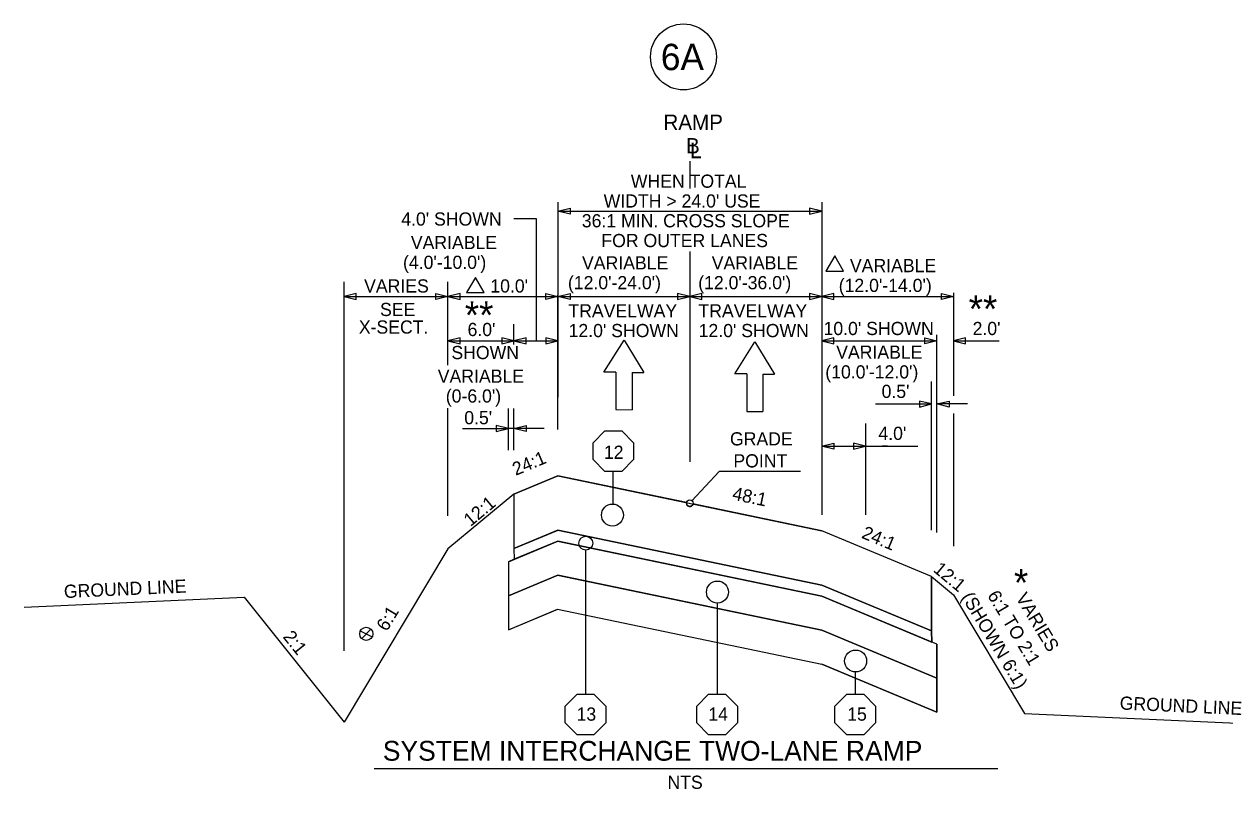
# Model space of a CAD drawing. Extents: x 4649 to 5578, y 4853 to 5383.
# Drawn here: x 5020.7 to 5130, y 5063.7 to 5133.3 of the extents above; entities that cross this region are included whole.
import ezdxf

# ---------------------------------------------------------------- set-up
doc = ezdxf.new("R2010")
doc.units = 0
for name, color, linetype in [('Level 25', 7, 'Continuous'), ('RD_QTY_Miscl_1', 7, 'Continuous'), ('RD_QTY_Miscl_2', 7, 'Continuous'), ('RD_QTY_Miscl_3', 7, 'Continuous'), ('RD_QTY_Miscl_4', 7, 'Continuous'), ('RD_SHT_Bndy', 7, 'Continuous'), ('RD_SHT_Typical', 7, 'Continuous'), ('RD_Sketch1', 7, 'Continuous'), ('RD_Sketch2', 7, 'Continuous'), ('RD_TX_TypSect', 7, 'Continuous')]:
    doc.layers.add(name, color=color, linetype=linetype)

msp = doc.modelspace()

# ---------------------------------------------------------------- linework, layer by layer
at = {"layer": 'Level 25'}
for p, q in [((5083.98, 5092.59), (5081.49, 5089.93)), ((5091.37, 5092.59), (5083.98, 5092.59))]:
    msp.add_line(p, q, dxfattribs=at)
msp.add_circle((5080.73, 5130.3), 3, dxfattribs=at)
at = {"layer": 'RD_QTY_Miscl_1'}
for p, q in [((5069.3, 5092.2), (5065.31, 5090.54)), ((5081.01, 5089.76), (5069.3, 5092.2)), ((5065.31, 5090.54), (5065.31, 5085.58)), ((5093.3, 5087.2), (5081.59, 5089.64)), ((5065.31, 5085.58), (5069.31, 5087.25)), ((5069.31, 5087.25), (5093.3, 5082.25)), ((5103.29, 5083.04), (5093.3, 5087.2)), ((5103.29, 5078.09), (5103.29, 5083.04)), ((5093.3, 5082.25), (5103.29, 5078.09))]:
    msp.add_line(p, q, dxfattribs=at)
msp.add_arc((5081.3, 5089.7), 0.3, 168.2319, 348.2319, dxfattribs=at)
at = {"layer": 'RD_QTY_Miscl_2'}
for p, q in [((5069.31, 5087.25), (5065.31, 5085.58)), ((5065.32, 5084.6), (5069.29, 5086.25)), ((5069.29, 5086.25), (5093.3, 5081.25)), ((5093.3, 5082.25), (5069.31, 5087.25)), ((5065.31, 5085.58), (5065.32, 5084.6)), ((5103.29, 5078.09), (5093.3, 5082.25)), ((5093.3, 5081.25), (5103.33, 5077.07)), ((5103.33, 5077.07), (5103.29, 5078.09))]:
    msp.add_line(p, q, dxfattribs=at)
at = {"layer": 'RD_QTY_Miscl_3'}
for p, q in [((5069.29, 5086.25), (5065.32, 5084.6)), ((5093.3, 5081.25), (5069.29, 5086.25)), ((5065.32, 5084.6), (5064.81, 5084.38)), ((5064.81, 5084.38), (5064.81, 5081.29)), ((5064.81, 5081.29), (5069.29, 5083.16)), ((5069.29, 5083.16), (5093.3, 5078.15)), ((5093.3, 5078.15), (5103.79, 5073.78)), ((5103.79, 5073.78), (5103.79, 5076.87))]:
    msp.add_line(p, q, dxfattribs=at)
msp.add_lwpolyline([(5103.79, 5076.87), (5103.33, 5077.07), (5093.3, 5081.25)], dxfattribs=at)
at = {"layer": 'RD_QTY_Miscl_4'}
for p, q in [((5069.29, 5083.16), (5064.81, 5081.29)), ((5093.3, 5078.15), (5069.29, 5083.16)), ((5064.81, 5081.29), (5064.81, 5078.2)), ((5064.81, 5078.2), (5069.28, 5080.06)), ((5069.28, 5080.06), (5093.3, 5075.06)), ((5103.79, 5073.78), (5093.3, 5078.15)), ((5093.3, 5075.06), (5103.79, 5070.68)), ((5103.79, 5070.68), (5103.79, 5073.78))]:
    msp.add_line(p, q, dxfattribs=at)
at = {"layer": 'RD_SHT_Bndy'}
for p, q in [((5073.5, 5101.62), (5075.32, 5104.54)), ((5075.32, 5104.54), (5077.11, 5101.61)), ((5085.39, 5101.46), (5087.22, 5104.37)), ((5087.22, 5104.37), (5089, 5101.45)), ((5074.59, 5101.62), (5073.5, 5101.62)), ((5074.59, 5101.62), (5074.59, 5098.22)), ((5076.05, 5101.61), (5077.11, 5101.61)), ((5076.05, 5101.61), (5076.05, 5098.21)), ((5086.49, 5101.46), (5085.39, 5101.46)), ((5086.49, 5101.46), (5086.49, 5098.06)), ((5087.94, 5101.45), (5089, 5101.45)), ((5087.94, 5101.45), (5087.94, 5098.05)), ((5074.59, 5098.22), (5076.05, 5098.21)), ((5086.49, 5098.06), (5087.94, 5098.05))]:
    msp.add_line(p, q, dxfattribs=at)
at = {"layer": 'RD_SHT_Typical'}
for p, q in [((5065.31, 5090.54), (5069.3, 5092.2)), ((5065.31, 5090.53), (5059.31, 5085.54)), ((5065.31, 5090.54), (5065.31, 5085.58)), ((5064.81, 5084.38), (5069.31, 5086.26)), ((5065.31, 5085.58), (5069.33, 5087.26)), ((5103.29, 5083.04), (5093.3, 5087.2)), ((5059.31, 5085.54), (5049.87, 5069.8)), ((5064.81, 5084.38), (5064.81, 5078.2)), ((5064.81, 5081.29), (5069.31, 5083.17)), ((5103.29, 5083.04), (5105.29, 5081.36)), ((5103.29, 5083.04), (5103.29, 5078.09)), ((5103.29, 5078.09), (5093.3, 5082.25)), ((5040.78, 5081.15), (5049.87, 5069.8)), ((5103.79, 5076.87), (5093.3, 5081.25)), ((5105.29, 5081.36), (5111.76, 5070.58)), ((5064.81, 5078.2), (5069.3, 5080.07)), ((5103.79, 5073.78), (5093.3, 5078.15)), ((5103.79, 5076.87), (5103.79, 5070.68)), ((5103.79, 5070.68), (5093.3, 5075.06))]:
    msp.add_line(p, q, dxfattribs=at)
for points in [[(5069.3, 5092.2), (5093.3, 5087.2)], [(5069.28, 5086.25), (5093.3, 5081.25)], [(5069.31, 5087.25), (5093.3, 5082.25)], [(5069.28, 5083.16), (5093.3, 5078.15)], [(5069.28, 5080.06), (5093.3, 5075.06)]]:
    msp.add_lwpolyline(points, dxfattribs=at)
at = {"layer": 'RD_Sketch1'}
for p, q in [((5020.75, 5080.24), (5040.78, 5081.15)), ((5111.76, 5070.58), (5133.85, 5069.57))]:
    msp.add_line(p, q, dxfattribs=at)
at = {"layer": 'RD_Sketch2'}
for points in [[(5076.19, 5095.21), (5076.19, 5093.68), (5075.11, 5092.6), (5073.58, 5092.6), (5072.5, 5093.68), (5072.5, 5095.21), (5073.58, 5096.29), (5075.11, 5096.29)], [(5073.67, 5071.25), (5073.67, 5069.72), (5072.59, 5068.64), (5071.06, 5068.64), (5069.98, 5069.72), (5069.98, 5071.25), (5071.06, 5072.33), (5072.59, 5072.33)], [(5085.63, 5071.25), (5085.63, 5069.72), (5084.55, 5068.64), (5083.02, 5068.64), (5081.93, 5069.72), (5081.93, 5071.25), (5083.02, 5072.33), (5084.55, 5072.33)], [(5098.2, 5071.25), (5098.2, 5069.72), (5097.12, 5068.64), (5095.59, 5068.64), (5094.51, 5069.72), (5094.51, 5071.25), (5095.59, 5072.33), (5097.12, 5072.33)]]:
    msp.add_lwpolyline(points, close=True, dxfattribs=at)
at = {"layer": 'RD_TX_TypSect'}
for p, q in [((5081.3, 5120.83), (5081.3, 5118.34)), ((5069.3, 5117.1), (5069.3, 5099.34)), ((5093.3, 5117.1), (5093.3, 5088.64)), ((5069.3, 5116.26), (5093.3, 5116.26)), ((5067.37, 5115.58), (5065.31, 5115.58)), ((5067.37, 5104.47), (5067.37, 5115.58)), ((5081.3, 5112.61), (5081.3, 5093.46)), ((5049.87, 5076.28), (5049.87, 5109.84)), ((5059.31, 5102.25), (5059.31, 5109.84)), ((5049.87, 5108.51), (5059.31, 5108.51)), ((5059.31, 5108.51), (5069.3, 5108.51)), ((5069.3, 5096.42), (5069.3, 5108.63)), ((5069.3, 5108.51), (5081.3, 5108.51)), ((5081.3, 5108.51), (5093.3, 5108.51)), ((5093.3, 5108.51), (5105.29, 5108.51)), ((5105.29, 5108.85), (5105.29, 5099.48)), ((5065.31, 5104.13), (5065.31, 5105.98)), ((5103.79, 5087.05), (5103.79, 5105.01)), ((5059.31, 5104.47), (5065.31, 5104.47)), ((5065.31, 5104.47), (5069.3, 5104.47)), ((5093.3, 5104.47), (5103.79, 5104.47)), ((5105.29, 5104.47), (5109.43, 5104.47)), ((5103.29, 5087.26), (5103.29, 5100.77)), ((5059.31, 5088.55), (5059.31, 5098.35)), ((5064.81, 5094.54), (5064.81, 5098.32)), ((5065.31, 5094.54), (5065.31, 5098.32)), ((5098.2, 5098.73), (5103.29, 5098.73)), ((5106.55, 5098.73), (5103.79, 5098.73)), ((5105.29, 5097.87), (5105.29, 5085.8)), ((5060.63, 5096.5), (5064.81, 5096.5)), ((5068.07, 5096.5), (5064.81, 5096.5)), ((5097.29, 5096.95), (5097.29, 5088.64)), ((5093.3, 5094.9), (5102.06, 5094.9)), ((5099.29, 5094.9), (5098.79, 5094.9)), ((5074.34, 5089.62), (5074.34, 5092.6)), ((5065.31, 5085.58), (5065.32, 5084.6)), ((5071.82, 5085.44), (5071.82, 5072.33)), ((5083.78, 5080.62), (5083.78, 5072.33)), ((5051.33, 5078.09), (5052.41, 5077.54)), ((5051.46, 5077.4), (5052.28, 5078.24)), ((5103.29, 5078.09), (5103.33, 5077.07)), ((5096.35, 5074.35), (5096.35, 5072.33)), ((5052.59, 5065.57), (5109.31, 5065.57))]:
    msp.add_line(p, q, dxfattribs=at)
for points in [[(5070.41, 5116.54), (5070.41, 5115.99), (5069.3, 5116.26)], [(5092.19, 5116.54), (5092.19, 5115.99), (5093.3, 5116.26)], [(5094.49, 5112.2), (5093.69, 5110.82), (5095.29, 5110.82)], [(5061.8, 5110.25), (5061, 5108.86), (5062.6, 5108.86)], [(5050.97, 5108.24), (5050.97, 5108.79), (5049.87, 5108.51)], [(5058.21, 5108.24), (5058.21, 5108.79), (5059.31, 5108.51)], [(5060.41, 5108.24), (5060.41, 5108.79), (5059.31, 5108.51)], [(5068.2, 5108.24), (5068.2, 5108.79), (5069.3, 5108.51)], [(5070.41, 5108.79), (5070.41, 5108.24), (5069.3, 5108.51)], [(5080.2, 5108.79), (5080.2, 5108.24), (5081.3, 5108.51)], [(5082.4, 5108.24), (5082.4, 5108.79), (5081.3, 5108.51)], [(5092.19, 5108.79), (5092.19, 5108.24), (5093.29, 5108.51)], [(5094.4, 5108.24), (5094.4, 5108.79), (5093.3, 5108.51)], [(5104.19, 5108.24), (5104.19, 5108.79), (5105.29, 5108.51)], [(5060.41, 5104.2), (5060.41, 5104.75), (5059.31, 5104.47)], [(5064.2, 5104.75), (5064.2, 5104.2), (5065.31, 5104.47)], [(5066.41, 5104.2), (5066.41, 5104.75), (5065.31, 5104.47)], [(5068.2, 5104.75), (5068.2, 5104.2), (5069.3, 5104.47)], [(5094.4, 5104.2), (5094.4, 5104.75), (5093.3, 5104.47)], [(5102.69, 5104.2), (5102.69, 5104.75), (5103.79, 5104.47)], [(5106.39, 5104.2), (5106.39, 5104.75), (5105.29, 5104.47)], [(5102.19, 5099), (5102.19, 5098.45), (5103.29, 5098.73)], [(5104.89, 5099), (5104.89, 5098.45), (5103.79, 5098.73)], [(5063.7, 5096.78), (5063.7, 5096.23), (5064.81, 5096.5)], [(5066.41, 5096.78), (5066.41, 5096.23), (5065.31, 5096.5)], [(5094.4, 5095.18), (5094.4, 5094.63), (5093.29, 5094.9)], [(5096.19, 5095.18), (5096.19, 5094.63), (5097.29, 5094.9)]]:
    msp.add_lwpolyline(points, close=True, dxfattribs=at)
for centre, radius in [((5074.27, 5088.63), 1), ((5081.3, 5089.7), 0.3), ((5071.84, 5086.07), 0.63), ((5083.82, 5081.62), 1), ((5051.88, 5077.82), 0.6), ((5096.39, 5075.35), 1)]:
    msp.add_circle(centre, radius, dxfattribs=at)

# ---------------------------------------------------------------- texts
at = {"layer": 'Level 25'}
for s, height, p in [('6A', 2.4, (5078.67, 5129.1)), ('RAMP', 1.4, (5078.91, 5123.66)), ('B ', 1.4, (5080.96, 5121.52)), ('GRADE', 1.2, (5084.96, 5094.96)), ('POINT', 1.2, (5085.27, 5092.96))]:
    msp.add_text(s, height=height, dxfattribs=at).set_placement(p)
at = {"layer": 'RD_TX_TypSect'}
for s, height, p in [('L', 1.4, (5081.33, 5121.09)), ("4.0' SHOWN", 1.2, (5055.06, 5114.96)), ('VARIES', 1.2, (5051.68, 5108.87)), ("10.0'", 1.2, (5063.16, 5108.87)), ('**', 2.5, (5060.84, 5105.57)), ('**', 2.5, (5106.67, 5106.13)), ('SEE', 1.2, (5053.13, 5106.73)), ('X-SECT.', 1.2, (5051.2, 5105.13)), ("6.0'", 1.2, (5061.09, 5104.91)), ("10.0' SHOWN", 1.2, (5093.47, 5105)), ("2.0'", 1.2, (5107.03, 5105)), ('SHOWN', 1.2, (5059.62, 5102.81)), ("0.5'", 1.2, (5098.75, 5099.28)), ("0.5'", 1.2, (5060.79, 5096.89)), ("4.0'", 1.2, (5098.46, 5095.46)), ('12', 1.2, (5073.49, 5093.74)), ('*', 2.5, (5110.79, 5081.23)), ('13', 1.2, (5071, 5069.92)), ('14', 1.2, (5082.99, 5069.92)), ('15', 1.2, (5095.62, 5069.92)), ('SYSTEM INTERCHANGE TWO-LANE RAMP', 1.8, (5053.38, 5066.28)), ('NTS', 1.2, (5079.27, 5063.72))]:
    msp.add_text(s, height=height, dxfattribs=at).set_placement(p)
for s, rotation, p in [('WHEN TOTAL', 0.0016, (5075.94, 5118.4)), ("WIDTH > 24.0' USE", 0.0016, (5073.47, 5116.6)), ('36:1 MIN. CROSS SLOPE', 0.0016, (5071.48, 5114.8)), ('VARIABLE', 0.0016, (5055.93, 5112.82)), ('FOR OUTER LANES', 0.0016, (5073.26, 5113)), ("(4.0'-10.0')", 0.0016, (5055.22, 5111.02)), ('VARIABLE', 0.0016, (5071.5, 5110.97)), ('VARIABLE', 0.0016, (5083.3, 5110.97)), ('VARIABLE', 0.0016, (5095.87, 5110.72)), ("(12.0'-24.0')", 0.0016, (5070.22, 5109.17)), ("(12.0'-36.0')", 0.0016, (5082.07, 5109.17)), ("(12.0'-14.0')", 0.0016, (5094.85, 5108.92)), ('TRAVELWAY', 0.0016, (5070.26, 5106.61)), ('TRAVELWAY', 0.0016, (5082.09, 5106.61)), ("12.0' SHOWN", 0.0016, (5070.28, 5104.81)), ("12.0' SHOWN", 0.0016, (5082.11, 5104.81)), ('VARIABLE', 0.0016, (5094.62, 5102.85)), ('VARIABLE', 0.0016, (5058.38, 5100.66)), ("(10.0'-12.0')", 0.0016, (5093.63, 5101.05)), ("(0-6.0')", 0.0016, (5059.11, 5098.86)), ('24:1', 22.619, (5065.47, 5092.19)), ('48:1', 348.2317, (5085.11, 5090.04)), ('12:1', 39.8056, (5061.36, 5087.53)), ('24:1', 337.3801, (5096.85, 5086.57)), ('12:1', 320.1939, (5103.37, 5083.55)), ('GROUND LINE', 2.6095, (5024.4, 5081.07)), ('(SHOWN 6:1)', 300.9638, (5105.98, 5081.17)), ('6:1 TO 2:1', 300.9638, (5108.33, 5081.32)), ('VARIES', 300.9638, (5110.91, 5081.11)), ('6:1', 59.0362, (5053.75, 5077.97)), ('2:1', 308.6598, (5044.24, 5077.53)), ('GROUND LINE', 357.3905, (5120.39, 5070.94))]:
    msp.add_text(s, height=1.2, rotation=rotation, dxfattribs=at).set_placement(p)

doc.saveas('drawing.dxf')
